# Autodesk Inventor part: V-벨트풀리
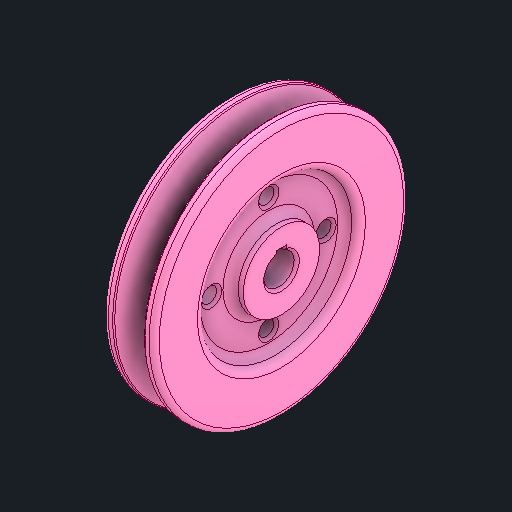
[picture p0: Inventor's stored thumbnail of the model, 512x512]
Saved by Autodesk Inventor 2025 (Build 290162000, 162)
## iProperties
Created: 2025-08
Part Number: V-벨트풀리
Material: 강철, 연강
Document SubType Name: Modeling
Designer: infra005
Density: 7.86 g/cm^3
Appearance: 기본값
Author: jhkim
Sending System: Autodesk Inventor 2026
Preprocessor: ST-DEVELOPER v20.1
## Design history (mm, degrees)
feature "솔리드1"
node "솔리드2"
